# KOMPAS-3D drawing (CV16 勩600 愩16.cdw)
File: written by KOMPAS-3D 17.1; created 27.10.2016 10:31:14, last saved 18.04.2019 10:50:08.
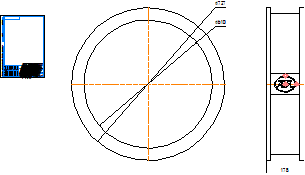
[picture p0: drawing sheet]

Sheet 1: A4, portrait

Title block, sheet 1: name: CV16 Ду600 Ру16; material: Внимание! Данный продукт является объектом авторского права ООО «Торговый Дом АДЛ». / Запрещается изменение, копирование, распространение / (в том числе путем копирования на другие сайты и ресурсы в Интернете) / или любое иное использование информации и объектов без предварительного / согласия правообладателя (ООО «Торговый Дом АДЛ»).; mass: 280,8; sheets: 1; organisation: ООО "Торговый дом АДЛ"; sheet format: A4; stored path: \\adlc.lan\data\АДЛ_ПКД\3D-модели\ADL production\Клапаны обратные ГРАНЛОК\CV16\KOMPAS 2D\CV16 Ду600 Ру16.cdw

Views: Вид 1, Проекционный вид 2
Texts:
  Klimkovich
  ADL
Dimensions and other numbers on the sheet: 727; 610; 178; 1:1; 1; 280,8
